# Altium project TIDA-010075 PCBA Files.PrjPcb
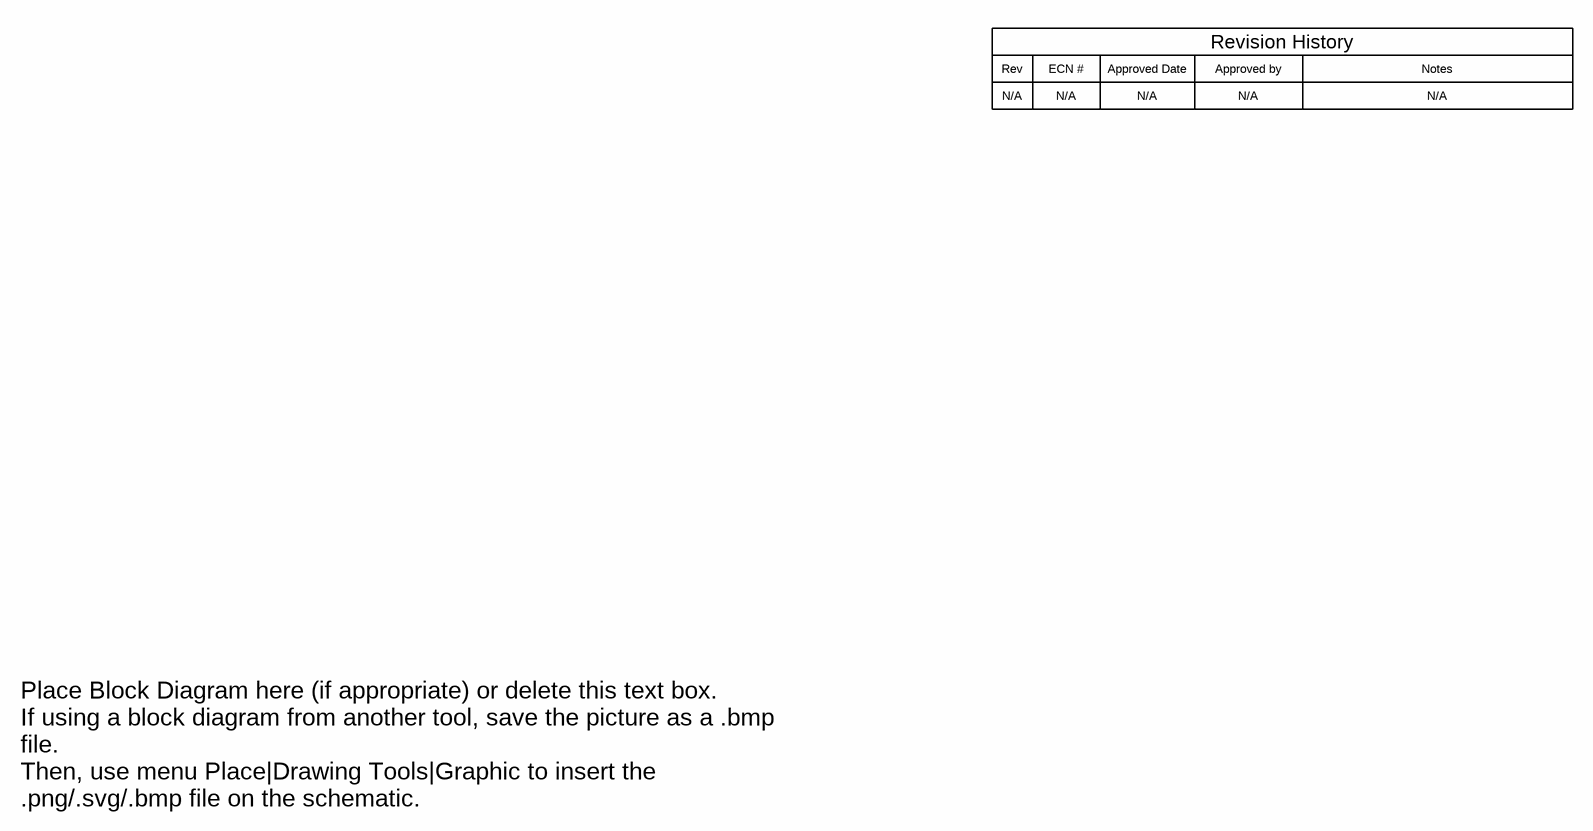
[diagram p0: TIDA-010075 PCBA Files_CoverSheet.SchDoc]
PCB_Layout: Bryan Liu; PRJ_Number: TIDA-010075; PRJ_Customer: Public Release; TID: TIDA-010075; TechSupport: http://www.ti.com/support; PRJ_Engineer: Bryan Liu; SCH_Rev: E1; PCB_Rev: E1; PRJ_Title: TPS54202 Battery Charger; CopyrightYear: 2018
3 sheets, 36 parts. Net scope: global (net labels, ports and power ports of the same name join across sheets).
Board file: TIDA-010075 PCBA Files_PCB.PcbDoc
Sheets:
  TIDA-010075 PCBA Files_CoverSheet.SchDoc
  TIDA-010075 PCBA Files_BlankSheet.SchDoc
  TIDA-010075 PCBA Files_EVM_Hardware.SchDoc

## Sheet TIDA-010075 PCBA Files_CoverSheet.SchDoc
size 431 x 279 mm; Date: Not shown in title block; ApprovedBy: Not shown in title block; CheckedBy: Not shown in title block; Author: Not shown in title block; CompanyName: Not shown in title block; Engineer: Not shown in title block; Organization: Not shown in title block; Address1: Not shown in title block; Address2: Not shown in title block; Address3: Not shown in title block; Address4: Not shown in title block; DocumentNumber: 1; Revision: Use project parameter SCH_Rev; SheetNumber: 1; SheetTotal: 3; PageSetup: Record=PageOptions¦CenterHorizontal=True¦CenterVertical=True¦PrintScale=1.00¦XCorrection=1.00¦YCorrection=1.00¦PrintKind=0¦BorderSize=5000000¦LeftOffset=0¦BottomOffset=0¦Orientation=2¦PaperLength=1000¦PaperWidth=1000¦Scale=100¦PaperSource=15¦PrintQuality=600¦MediaType=1¦DitherType=10¦PaperKind=Letter¦PrintScaleMode=1

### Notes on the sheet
- Rev
- N/A
- ECN #
- Approved Date
- Approved by
- Revision History
- Notes
- Place Block Diagram here (if appropriate) or delete this text box.
  If using a block diagram from another tool, save the picture as a .bmp file.
  Then, use menu Place|Drawing Tools|Graphic to insert the .png/.svg/.bmp file on the schematic.

## Sheet TIDA-010075 PCBA Files_BlankSheet.SchDoc
size 431 x 304 mm; Date: Not shown in title block; ApprovedBy: Not shown in title block; CheckedBy: Not shown in title block; Author: Not shown in title block; CompanyName: Not shown in title block; Engineer: Not shown in title block; Organization: Not shown in title block; Address1: Not shown in title block; Address2: Not shown in title block; Address3: Not shown in title block; Address4: Not shown in title block; DocumentNumber: 1; Revision: Use project parameter SCH_Rev; SheetNumber: 2; SheetTotal: 3; PageSetup: Record=PageOptions¦CenterHorizontal=True¦CenterVertical=True¦PrintScale=1.00¦XCorrection=1.00¦YCorrection=1.00¦PrintKind=0¦BorderSize=5000000¦LeftOffset=0¦BottomOffset=0¦Orientation=2¦PaperLength=1000¦PaperWidth=1000¦Scale=100¦PaperSource=15¦PrintQuality=600¦MediaType=1¦DitherType=10¦PaperKind=Letter¦PrintScaleMode=1
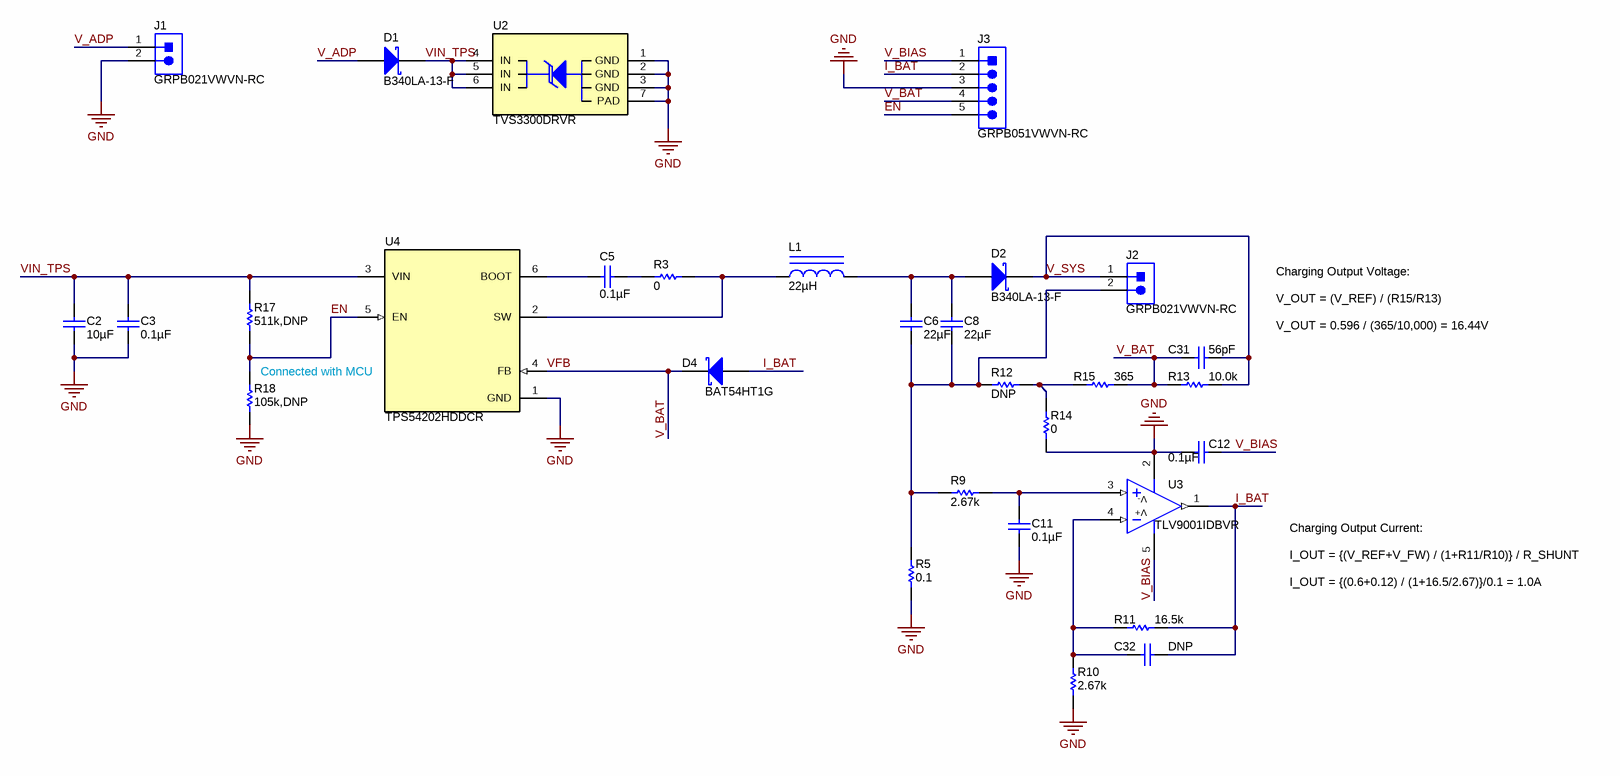
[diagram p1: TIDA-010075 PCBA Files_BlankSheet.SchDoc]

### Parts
C2  ValueDisplayed: 10µF  [0805_HV]  (hidden comment: GRM21BR6YA106KE43L)
C3  ValueDisplayed: 0.1µF  [0603]  (hidden comment: 06035C104KAT2A)
C5  ValueDisplayed: 0.1µF  [0603]  (hidden comment: 06035C104KAT2A)
C6  ValueDisplayed: 22µF  [0805_HV]  (hidden comment: C2012X5R1V226M125AC)
C8  ValueDisplayed: 22µF  [0805_HV]  (hidden comment: C2012X5R1V226M125AC)
C11  ValueDisplayed: 0.1µF  [0402]  (hidden comment: GRM155R71C104KA88D)
C12  ValueDisplayed: 0.1µF  [0402]  (hidden comment: GRM155R71C104KA88D)
C31  ValueDisplayed: 56pF  [0402]  (hidden comment: GRM1555C1E560JA01D)
C32  ValueDisplayed: DNP  [0402]  (hidden comment: 885012005009)
D1  B340LA-13-F  [SMA]
D2  B340LA-13-F  [SMA]
D4  BAT54HT1G  [SOD-323]
J1  GRPB021VWVN-RC  [Sullins_GRPB021VWVN-RC]
J2  GRPB021VWVN-RC  [Sullins_GRPB021VWVN-RC]
J3  GRPB051VWVN-RC  [Sullins_GRPB051VWVN-RC]
L1  ValueDisplayed: 22µH  [THPC6045MF]  (hidden comment: THPC6045MF-220M)
R3  ValueDisplayed: 0  [0603]  (hidden comment: MCR03EZPJ000)
R5  ValueDisplayed: 0.1  [1206]  (hidden comment: CRM1206-FX-R100ELF)
R9  ValueDisplayed: 2.67k  [0402]  (hidden comment: CRCW04022K67FKED)
R10  ValueDisplayed: 2.67k  [0402]  (hidden comment: CRCW04022K67FKED)
R11  ValueDisplayed: 16.5k  [0402]  (hidden comment: CRCW040216K5FKED)
R12  ValueDisplayed: DNP  [0402]  (hidden comment: CRCW04020000Z0ED)
R13  ValueDisplayed: 10.0k  [0402]  (hidden comment: CRCW040210K0FKED)
R14  ValueDisplayed: 0  [0402]  (hidden comment: CRCW04020000Z0ED)
R15  ValueDisplayed: 365  [0402]  (hidden comment: CRCW0402365RFKED)
R17  ValueDisplayed: 511k,DNP  [0603]  (hidden comment: CRCW06031K00FKEA)
R18  ValueDisplayed: 105k,DNP  [0603]  (hidden comment: CRCW06031K00FKEA)
U2  TVS3300DRVR  [DRV0006A]
U3  TLV9001IDBVR  [DBV0005A_N]
U4  TPS54202HDDCR  [DDC0006A_N]

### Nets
GND: C2.2 C3.2 C11.2 C12.1 J1.2 J3.3 R5.1 R10.1 R14.1 R18.1 U2.1(GND) U2.2(GND) U2.3(GND) U2.7(PAD) U3.2(V-) U4.1(GND)
EN: J3.5 R17.1 R18.2 U4.5(EN)
I_BAT: C32.1 D4.2(A) J3.2 R11.2 U3.1(OUT)
V_ADP: D1.2(A) J1.1
V_BAT: C31.2 D4.1(K) J3.4 R13.1 R15.2 U4.4(FB)  [also labelled VFB]
V_BIAS: C12.2 J3.1 U3.5(V+)
V_SYS: C31.1 D2.1(K) J2.1 R13.2
VIN_TPS: C2.1 C3.1 D1.1(K) R17.2 U2.4(IN) U2.5(IN) U2.6(IN) U4.3(VIN)
NetC5_1: C5.1 R3.1
NetC5_2: C5.2 U4.6(BOOT)
NetC6_1: C6.1 C8.1 D2.2(A) L1.2
NetC6_2: C6.2 C8.2 J2.2 R5.2 R9.2 R12.1
NetC11_1: C11.1 R9.1 U3.3(IN+)
NetC32_2: C32.2 R10.2 R11.1 U3.4(IN-)
NetL1_1: L1.1 R3.2 U4.2(SW)
NetR12_2: R12.2 R14.2 R15.1

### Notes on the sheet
- Charging Output Voltage:
  V_OUT = (V_REF) / (R15/R13)
  V_OUT = 0.596 / (365/10,000) = 16.44V
- Connected with MCU
- Charging Output Current:
  I_OUT = {(V_REF+V_FW) / (1+R11/R10)} / R_SHUNT
  I_OUT = {(0.6+0.12) / (1+16.5/2.67)}/0.1 = 1.0A

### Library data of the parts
C2 = GRM21BR6YA106KE43L: CAP, CERM, 10 µF, 35 V,+/- 10%, X5R, 0805; Manufacturer: MuRata; Polarized: N; CompType: Capacitor; Value: 10uF; U/M: EA; Cap_F: 0.00001; Tolerance_%: 10; VDC_V: 35; Value2: 35V; TaMin_C: -55; TaMax_C: 85; Cap_Case: 0805; SizeArea_mm2: 2.5; SizeAreaWB_mm2: 6.75; SizeX_mm: 2; SizeY_mm: 1.25; SizeZ_mm: 1.45; AEC Category: Q200; Green_Lifecycle: Active; Green_REACh: Passed
C3 C5 = 06035C104KAT2A: CAP, CERM, 0.1 µF, 50 V,+/- 10%, X7R, 0603; Manufacturer: AVX; Polarized: N; CompType: Capacitor; Value: 0.1uF; U/M: EA; Cap_F: 0.0000001; Tolerance_%: 10; VDC_V: 50; Value2: 50V; TaMin_C: -55; TaMax_C: 125; SizeArea_mm2: 1.28; SizeAreaWB_mm2: 4.68; SizeX_mm: 1.6; SizeY_mm: 0.8; SizeZ_mm: 1; AEC Category: Q200; Green_Lifecycle: Active; Green_REACh: Passed
C6 C8 = C2012X5R1V226M125AC: CAP, CERM, 22 µF, 35 V,+/- 20%, X5R, 0805; Manufacturer: TDK; Polarized: N; CompType: Capacitor; Value: 22uF; U/M: EA; Cap_F: 0.000022; Tolerance_%: 20; ESR_ohm: 0.00205; Value1: 0.00205 ohm; VDC_V: 35; Value2: 35V; IRMS_A: 4.55587; TaMin_C: -55; TaMax_C: 85; Cap_Case: 0805; SizeArea_mm2: 2.5; SizeAreaWB_mm2: 6.75; SizeX_mm: 2; SizeY_mm: 1.25; SizeZ_mm: 1.45; AEC Category: Q200; Green_Lifecycle: Active; Green_REACh: Passed
C11 C12 = GRM155R71C104KA88D: CAP, CERM, 0.1 µF, 16 V,+/- 10%, X7R, 0402; Manufacturer: MuRata; Polarized: N; CompType: Capacitor; Value: 0.1uF; U/M: EA; Cap_F: 0.0000001; Tolerance_%: 10; VDC_V: 16; Value2: 16V; TaMin_C: -55; TaMax_C: 125; SizeArea_mm2: 0.5; SizeAreaWB_mm2: 3; SizeX_mm: 1; SizeZ_mm: 0.6; AEC Category: Q200; Green_Lifecycle: Active; Green_REACh: Passed
C31 = GRM1555C1E560JA01D: CAP, CERM, 56 pF, 25 V,+/- 5%, C0G/NP0, 0402; Manufacturer: MuRata; Polarized: N; CompType: Capacitor; Value: 56pF; U/M: EA; Cap_F: 0.000000000056; Tolerance_%: 5; VDC_V: 25; Value2: 25V; TaMin_C: -55; TaMax_C: 125; SizeArea_mm2: 0.5; SizeAreaWB_mm2: 3; SizeX_mm: 1; SizeZ_mm: 0.6; AEC Category: Q200
C32 = 885012005009: CAP, CERM, 22 pF, 10 V,+/- 5%, C0G/NP0, 0402; Manufacturer: Wurth Elektronik; Polarized: N; CompType: Capacitor; Value: 22pF; U/M: EA; Cap_F: 0.000000000022; Tolerance_%: 5; VDC_V: 10; Value2: 10V; TaMin_C: -55; TaMax_C: 125; SizeArea_mm2: 0.5; SizeAreaWB_mm2: 3; SizeX_mm: 1; SizeZ_mm: 0.6; AEC Category: Q200
D1 D2 = CMP-0028413-2: Diode, Schottky, 40 V, 3 A, SMA; Manufacturer: Diodes Inc.; TJmax_C: 125°C; AEC Category: Q101; RJC_CperW: 25; Green_Lifecycle: Not Set; Value2: 0.45V; SizeZ_mm: 2.87; Green_REACh: Incomplete; Value1: 3A; SizeX_mm: 5.59; Vf_V: 4.5dV; SizeArea_mm2: 16.3228; Value: 40V; SizeAreaWB_mm2: 37.3428; SizeY_mm: 2.92
D4 = CMP-0028455-2: Diode, Schottky, 30 V, 0.2 A, SOD-323; Manufacturer: ON Semiconductor; Vr_V: 30V; Value: 30V; SizeZ_mm: 1; Value1: 0.2A; SizeAreaWB_mm2: 8.695; Vf_V: 3.5dV; Io_A: 2dA; SizeX_mm: 2.7; SizeY_mm: 1.35; Green_Lifecycle: Active; AEC Category: Q101; Value2: 0.35V; SizeArea_mm2: 3.645; Green_REACh: Passed
J1 J2 = GRPB021VWVN-RC: Header, 50mil, 2x1, Gold, TH; Manufacturer: Sullins Connector Solutions; SymbolCreator: a0412235; Green_Lifecycle: Not Set; Green_REACh: Incomplete
J3 = GRPB051VWVN-RC: Header, 50mil, 5x1, Gold, TH; Manufacturer: Sullins Connector Solutions; SymbolCreator: a0412235
L1 = THPC6045MF-220M: Inductor, Ferrite, 22 µH, 1.9 A, 0.096 ohm, SMD; Manufacturer: Tai-Tech; Value: 22uH; Ind_H: 22.0E-6; Imax_A: 1.9; Irms: 1.9A @ 40C rise; Isat: 2.7A @ 30% inductance drop; DCR_ohm: 0.096; Value2: 1.9A; AEC Category: Q200; AEC Qualified: N
R3 = CMP-0025883-3: RES, 0, 5%, 0.1 W, 0603; Manufacturer: Rohm; Power_W: 100mW; TempCo: 400 ppm/C; Value_Code: 0000; U/M: EA; Value: 0; EIA_Code: E24; SizeX_mm: 1.6; SizeY_mm: 0.8; SizeZ_mm: 1; Value2: 0.1W; SizeArea_mm2: 1.28; AEC Qualified: N; VDC_V: 50V; AEC Category: Q200
R5 = CRM1206-FX-R100ELF: RES, 0.1, 1%, 0.5 W, 1206; Manufacturer: Bourns; CompType: Resistor; Value: 0.1; Value_Code: R100; Tolerance_%: 1; Power_W: 0.5; Value2: 0.5W; VDC_V: 0; TempCo: 150 ppm/C; SizeArea_mm2: 5.12; SizeX_mm: 3.2; SizeY_mm: 1.6; SizeZ_mm: 1.35; EIA_Code: E96; U/M: EA; AEC Category: Q200
R9 R10 = CRCW04022K67FKED: RES, 2.67 k, 1%, 0.063 W, 0402; Manufacturer: Vishay-Dale; CompType: Resistor; Value: 2.67k; Res_ohm: 2670; Value_Code: 2k67; Tolerance_%: 1; Power_W: 0.063; Value2: 0.063W; VDC_V: 50; TempCo: 100 ppm/C; SizeArea_mm2: 0.5; SizeZ_mm: 0.6; EIA_Code: E96; U/M: EA; AEC Category: Q200
R11 = CRCW040216K5FKED: RES, 16.5 k, 1%, 0.063 W, 0402; Manufacturer: Vishay-Dale; CompType: Resistor; Value: 16.5k; Res_ohm: 16500; Value_Code: 16k5; Tolerance_%: 1; Power_W: 0.063; Value2: 0.063W; VDC_V: 50; TempCo: 100 ppm/C; SizeArea_mm2: 0.5; SizeZ_mm: 0.6; EIA_Code: E96; U/M: EA; AEC Category: Q200; Green_Lifecycle: Active; Green_REACh: Passed
R12 R14 = CRCW04020000Z0ED: RES, 0, 5%, 0.063 W, 0402; Manufacturer: Vishay-Dale; CompType: Resistor; Value: 0; Value_Code: 0000; Tolerance_%: 5; Power_W: 0.063; Value2: 0.063W; VDC_V: 50; TempCo: 200 ppm/C; SizeArea_mm2: 0.5; SizeX_mm: 1; SizeZ_mm: 0.6; EIA_Code: E24; U/M: EA; AEC Category: Q200; Green_Lifecycle: Active; Green_REACh: Passed
R13 = CRCW040210K0FKED: RES, 10.0 k, 1%, 0.063 W, 0402; Manufacturer: Vishay-Dale; CompType: Resistor; Value: 10.0k; Res_ohm: 10000; Value_Code: 10k0; Tolerance_%: 1; Power_W: 0.063; Value2: 0.063W; VDC_V: 50; TempCo: 100 ppm/C; SizeArea_mm2: 0.5; SizeZ_mm: 0.6; EIA_Code: E96; U/M: EA; AEC Category: Q200; Green_Lifecycle: Active; Green_REACh: Passed
R15 = CRCW0402365RFKED: RES, 365, 1%, 0.063 W, 0402; Manufacturer: Vishay-Dale; CompType: Resistor; Value: 365; Value_Code: 365R; Tolerance_%: 1; Power_W: 0.063; Value2: 0.063W; VDC_V: 50; TempCo: 100 ppm/C; SizeArea_mm2: 0.5; SizeZ_mm: 0.6; EIA_Code: E96; U/M: EA; AEC Category: Q200; Green_Lifecycle: Active; Green_REACh: Passed
R17 R18 = CRCW06031K00FKEA: RES, 1.00 k, 1%, 0.1 W, 0603; Manufacturer: Vishay-Dale; CompType: Resistor; Value: 1.00k; Res_ohm: 1000; Value_Code: 1k00; Tolerance_%: 1; Power_W: 0.1; Value2: 0.1W; VDC_V: 75; TempCo: 100 ppm/C; SizeArea_mm2: 1.28; SizeX_mm: 1.6; SizeY_mm: 0.8; EIA_Code: E96; U/M: EA; AEC Category: Q200; Green_Lifecycle: Active; Green_REACh: Passed
U2 = TVS3300DRVR: 33V Precision Surge Protection Clamp, DRV0006A (WSON-6); Alternate PartNumber: TVS3300DRVT; Manufacturer: Texas Instruments; SymbolCreator: Altium; SizeArea_mm2: 4; SizeAreaWB_mm2: 9; SizeX_mm: 2; SizeZ_mm: 0.8; CompType: IC; U/M: EA
U3 = CMP-0081550-1: Low-Power, Rail-to-Rail In and Out, 1-MHz Operational Amplifier, DBV0005A (SOT-23-5); Alternate PartNumber: TLV9001IDBVT; Alternate Manufacturer: Texas Instruments; SizeAreaWB_mm2: 14.82; SizeZ_mm: 1.45; SizeX_mm: 2.8; SizeY_mm: 2.9; SizeArea_mm2: 8.12; CompType: IC; AEC Qualified: N; AEC Category: Q200
U4 = CMP-0074516-2: 4.5-V TO 28-V INPUT, 2-A OUTPUT, EMI FRIENDLY SYNCHRONUOUS STEP-DOWN CONVERTOR, DDC0006A (SOT-23-T-6); Alternate PartNumber: TPS54202HDDCT; Manufacturer: Texas Instruments; SizeZ_mm: 0.87; SizeX_mm: 1.65; SizeY_mm: 2.95; SizeArea_mm2: 4.8675; CompType: IC; U/M: EA; SizeAreaWB_mm2: 10.4675

## Sheet TIDA-010075 PCBA Files_EVM_Hardware.SchDoc
size 431 x 279 mm; Date: Not shown in title block; ApprovedBy: Not shown in title block; CheckedBy: Not shown in title block; Author: Not shown in title block; CompanyName: Not shown in title block; Engineer: Not shown in title block; Organization: Not shown in title block; Address1: Not shown in title block; Address2: Not shown in title block; Address3: Not shown in title block; Address4: Not shown in title block; DocumentNumber: 1; Revision: Use project parameter SCH_Rev; SheetNumber: 3; SheetTotal: 3; PageSetup: Record=PageOptions¦CenterHorizontal=True¦CenterVertical=True¦PrintScale=1.00¦XCorrection=1.00¦YCorrection=1.00¦PrintKind=0¦BorderSize=5000000¦LeftOffset=0¦BottomOffset=0¦Orientation=2¦PaperLength=1000¦PaperWidth=1000¦Scale=100¦PaperSource=15¦PrintQuality=600¦MediaType=1¦DitherType=10¦PaperKind=Letter¦PrintScaleMode=1
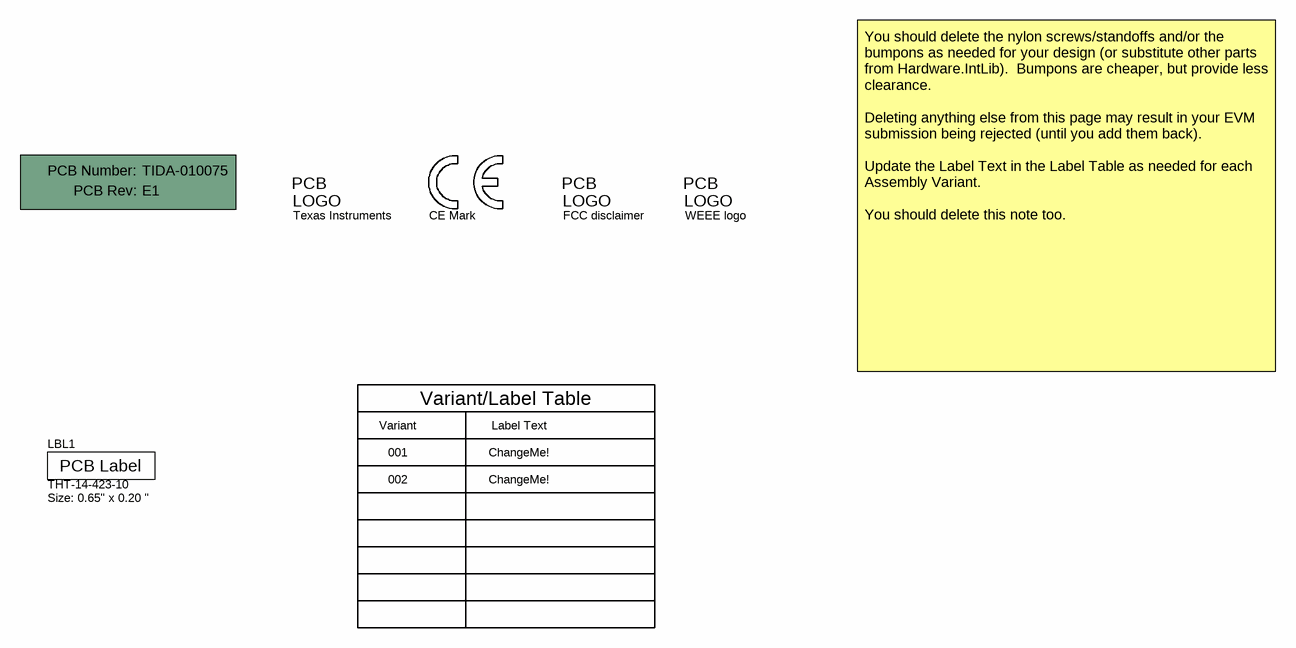
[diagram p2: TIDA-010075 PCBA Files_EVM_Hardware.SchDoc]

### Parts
!PCB  Printed Circuit Board  (value not drawn)  (mechanical)
LBL1  THT-14-423-10  Note: Size: 0.65" x 0.20 "  [Label_650x200]
Logo1  Texas Instruments  [TI_Stacked_Overlay_Small]  (no BOM)
Logo2  CE Mark  [CE_Mark_5mm]  (no BOM)
Logo3  FCC disclaimer  [FCC_disclaimer]  (no BOM)
Logo4  WEEE logo  [WEEE_Minimum]  (no BOM)

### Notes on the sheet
- Variant
- Variant/Label Table
- Label Text
- You should delete the nylon screws/standoffs and/or the bumpons as needed for your design (or substitute other parts from Hardware.IntLib).  Bumpons are cheaper, but provide less clearance.
  Deleting anything else from this page may result in your EVM submission being rejected (until you add them back).
  Update the Label Text in the Label Table as needed for each Assembly Variant.
  You should delete this note too.
- 001
- 002
- ChangeMe!

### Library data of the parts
!PCB = CMP-0003618-2: Manufacturer: Any; PartNumber: TIDA-010075
LBL1 = CMP-0003625-1: Thermal Transfer Printable Labels, 0.650" W x 0.200" H - 10,000 per roll; Manufacturer: Brady; CompType: Label
Logo1 = CMP-0074838-1: Texas Instrument Corporate Signature; SymbolCreator: a0412235; Lib Reference: TI_Logo; Library Reference: Logo
Logo2 = CMP-0074844-1: SymbolCreator: a0412235
Logo3 = CMP-0074847-1: FCC_disclaimer; Library Reference: Logo
Logo4 = CMP-0074769-1

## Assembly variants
001: not fitted FID1 FID2 FID3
